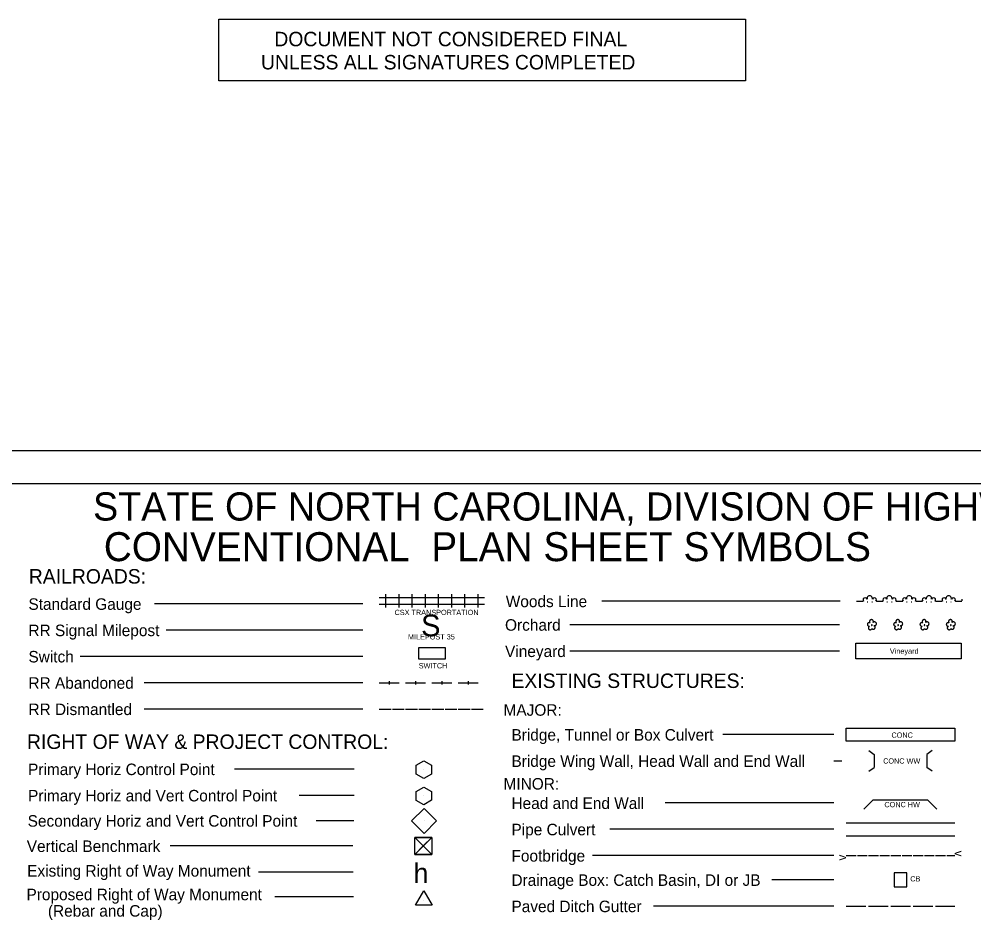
# Model space of a CAD drawing. Extents: x 885291.5 to 885334, y 651348 to 651383.7.
# Drawn here: x 885305.76 to 885323.9, y 651366.57 to 651383.73 of the extents above; entities that cross this region are included whole.
import ezdxf

# ---------------------------------------------------------------- set-up
doc = ezdxf.new("R2010")
doc.units = 0
for name, color, linetype in [('Default', 7, 'Continuous'), ('Sheet Sticker Exception Certification CELL', 7, 'Continuous'), ('Sheet Symbology CELL', 7, 'Continuous'), ('Stewart Plot Border Xerox6279 and LJ5000', 7, 'Continuous')]:
    doc.layers.add(name, color=color, linetype=linetype)

msp = doc.modelspace()

# ---------------------------------------------------------------- linework, layer by layer
at = {"layer": 'Default'}
for p, q in [((885313.448, 651369.463), (885313.448, 651369.463)), ((885313.448, 651368.964), (885313.448, 651368.964)), ((885313.451, 651368.487), (885313.451, 651368.487)), ((885313.439, 651368.012), (885313.439, 651368.012))]:
    msp.add_line(p, q, dxfattribs=at)
for points in [[(885313.448, 651369.297), (885313.303, 651369.379), (885313.303, 651369.546), (885313.448, 651369.63), (885313.593, 651369.547), (885313.593, 651369.379), (885313.448, 651369.297)], [(885313.601, 651368.174), (885313.276, 651367.85), (885313.438, 651368.012), (885313.601, 651367.85), (885313.276, 651368.174)], [(885313.438, 651368.012), (885313.601, 651368.174), (885313.276, 651368.174), (885313.438, 651368.012)], [(885313.438, 651368.012), (885313.276, 651367.85), (885313.601, 651367.85), (885313.438, 651368.012)]]:
    msp.add_lwpolyline(points, dxfattribs=at)
for points in [[(885313.302, 651369.049), (885313.449, 651369.13), (885313.595, 651369.05), (885313.593, 651368.882), (885313.446, 651368.796), (885313.302, 651368.878)], [(885313.216, 651368.488), (885313.452, 651368.724), (885313.689, 651368.488), (885313.453, 651368.251)], [(885313.276, 651368.174), (885313.601, 651368.174), (885313.601, 651367.85), (885313.276, 651367.85)]]:
    msp.add_lwpolyline(points, close=True, dxfattribs=at)
at = {"layer": 'Sheet Sticker Exception Certification CELL'}
for p, q in [((885309.555, 651382.553), (885309.555, 651383.728)), ((885309.555, 651383.728), (885319.556, 651383.728)), ((885319.556, 651383.727), (885319.556, 651382.552)), ((885319.556, 651382.553), (885309.555, 651382.553))]:
    msp.add_line(p, q, dxfattribs=at)
at = {"layer": 'Sheet Symbology CELL'}
for p, q in [((885312.602, 651372.732), (885312.852, 651372.732)), ((885312.727, 651372.545), (885312.727, 651372.795)), ((885312.852, 651372.732), (885313.102, 651372.732)), ((885312.977, 651372.545), (885312.977, 651372.795)), ((885313.102, 651372.732), (885313.352, 651372.732)), ((885313.227, 651372.545), (885313.227, 651372.795)), ((885313.352, 651372.732), (885313.602, 651372.732)), ((885313.477, 651372.545), (885313.477, 651372.795)), ((885313.602, 651372.732), (885313.852, 651372.732)), ((885313.727, 651372.545), (885313.727, 651372.795)), ((885313.852, 651372.732), (885314.102, 651372.732)), ((885313.977, 651372.545), (885313.977, 651372.795)), ((885314.102, 651372.732), (885314.352, 651372.732)), ((885314.227, 651372.545), (885314.227, 651372.795)), ((885314.352, 651372.732), (885314.602, 651372.732)), ((885314.477, 651372.545), (885314.477, 651372.795)), ((885321.358, 651372.664), (885316.83, 651372.664)), ((885321.668, 651372.664), (885321.793, 651372.664)), ((885321.866, 651372.652), (885321.879, 651372.652)), ((885321.954, 651372.652), (885321.966, 651372.652)), ((885322.043, 651372.664), (885322.168, 651372.664)), ((885322.241, 651372.652), (885322.254, 651372.652)), ((885322.329, 651372.652), (885322.341, 651372.652)), ((885322.418, 651372.664), (885322.543, 651372.664)), ((885322.616, 651372.652), (885322.629, 651372.652)), ((885322.704, 651372.652), (885322.716, 651372.652)), ((885322.793, 651372.664), (885322.918, 651372.664)), ((885322.991, 651372.652), (885323.004, 651372.652)), ((885323.079, 651372.652), (885323.091, 651372.652)), ((885323.168, 651372.664), (885323.293, 651372.664)), ((885323.366, 651372.652), (885323.379, 651372.652)), ((885323.454, 651372.652), (885323.466, 651372.652)), ((885323.543, 651372.664), (885323.668, 651372.664)), ((885312.292, 651372.613), (885308.332, 651372.613)), ((885312.602, 651372.607), (885312.852, 651372.607)), ((885312.852, 651372.607), (885313.102, 651372.607)), ((885313.102, 651372.607), (885313.352, 651372.607)), ((885313.352, 651372.607), (885313.602, 651372.607)), ((885313.602, 651372.607), (885313.852, 651372.607)), ((885313.852, 651372.607), (885314.102, 651372.607)), ((885314.102, 651372.607), (885314.352, 651372.607)), ((885314.352, 651372.607), (885314.602, 651372.607)), ((885312.292, 651372.113), (885308.553, 651372.113)), ((885321.344, 651372.216), (885316.22, 651372.216)), ((885312.292, 651371.613), (885306.919, 651371.613)), ((885321.344, 651371.716), (885316.22, 651371.716)), ((885312.292, 651371.113), (885308.138, 651371.113)), ((885312.602, 651371.113), (885312.977, 651371.113)), ((885312.789, 651371.144), (885312.789, 651371.082)), ((885313.102, 651371.113), (885313.477, 651371.113)), ((885313.289, 651371.144), (885313.289, 651371.082)), ((885313.602, 651371.113), (885313.977, 651371.113)), ((885313.789, 651371.144), (885313.789, 651371.082)), ((885314.102, 651371.113), (885314.477, 651371.113)), ((885314.289, 651371.144), (885314.289, 651371.082)), ((885312.292, 651370.613), (885308.138, 651370.613)), ((885312.292, 651370.613), (885308.138, 651370.613)), ((885312.602, 651370.613), (885312.827, 651370.613)), ((885312.852, 651370.613), (885313.077, 651370.613)), ((885313.102, 651370.613), (885313.327, 651370.613)), ((885313.352, 651370.613), (885313.577, 651370.613)), ((885313.602, 651370.613), (885313.827, 651370.613)), ((885313.852, 651370.613), (885314.077, 651370.613)), ((885314.102, 651370.613), (885314.327, 651370.613)), ((885314.352, 651370.613), (885314.577, 651370.613)), ((885321.236, 651370.128), (885319.125, 651370.128)), ((885321.897, 651369.825), (885322, 651369.753)), ((885322, 651369.753), (885322, 651369.503)), ((885323.102, 651369.825), (885323, 651369.753)), ((885323, 651369.753), (885323, 651369.503)), ((885321.236, 651369.628), (885321.386, 651369.628)), ((885312.125, 651369.473), (885309.849, 651369.473)), ((885321.897, 651369.432), (885322, 651369.503)), ((885323.102, 651369.432), (885323, 651369.503)), ((885312.125, 651368.973), (885311.077, 651368.973)), ((885321.807, 651368.714), (885321.984, 651368.891)), ((885321.984, 651368.891), (885323.015, 651368.891)), ((885323.015, 651368.891), (885323.192, 651368.714)), ((885321.236, 651368.829), (885318.028, 651368.829)), ((885312.117, 651368.492), (885311.403, 651368.492)), ((885321.236, 651368.329), (885316.981, 651368.329)), ((885321.468, 651368.454), (885323.531, 651368.454)), ((885321.468, 651368.204), (885323.531, 651368.204)), ((885312.1, 651368.012), (885308.629, 651368.012)), ((885321.236, 651367.829), (885316.649, 651367.829)), ((885321.468, 651367.829), (885321.656, 651367.829)), ((885321.681, 651367.829), (885321.868, 651367.829)), ((885321.893, 651367.829), (885322.081, 651367.829)), ((885322.106, 651367.829), (885322.293, 651367.829)), ((885322.318, 651367.829), (885322.506, 651367.829)), ((885322.531, 651367.829), (885322.718, 651367.829)), ((885322.743, 651367.829), (885322.931, 651367.829)), ((885322.956, 651367.829), (885323.143, 651367.829)), ((885323.168, 651367.829), (885323.356, 651367.829)), ((885323.381, 651367.829), (885323.531, 651367.829)), ((885312.108, 651367.512), (885310.306, 651367.512)), ((885321.236, 651367.368), (885320.056, 651367.368)), ((885312.11, 651367.043), (885310.617, 651367.043)), ((885313.448, 651366.977), (885313.448, 651366.977)), ((885321.236, 651366.868), (885317.812, 651366.868)), ((885321.468, 651366.868), (885321.843, 651366.868)), ((885321.893, 651366.868), (885322.268, 651366.868)), ((885322.318, 651366.868), (885322.693, 651366.868)), ((885322.743, 651366.868), (885323.118, 651366.868)), ((885323.168, 651366.868), (885323.531, 651366.868))]:
    msp.add_line(p, q, dxfattribs=at)
for points in [[(885333.401, 651374.896), (885295.901, 651374.896), (885295.901, 651348.671), (885333.401, 651348.671)], [(885313.352, 651371.787), (885313.852, 651371.787), (885313.852, 651371.56), (885313.352, 651371.56)], [(885322.379, 651367.235), (885322.62, 651367.235), (885322.62, 651367.501), (885322.379, 651367.501)], [(885313.292, 651366.887), (885313.448, 651367.157), (885313.604, 651366.887)]]:
    msp.add_lwpolyline(points, close=True, dxfattribs=at)
for points in [[(885321.98, 651372.26), (885321.984, 651372.267), (885321.985, 651372.275), (885321.984, 651372.282), (885321.982, 651372.29), (885321.979, 651372.296), (885321.975, 651372.302), (885321.969, 651372.307), (885321.962, 651372.311), (885321.954, 651372.314), (885321.947, 651372.314), (885321.94, 651372.312), (885321.932, 651372.31), (885321.926, 651372.306), (885321.92, 651372.301), (885321.916, 651372.294), (885321.914, 651372.287), (885321.912, 651372.28), (885321.912, 651372.272), (885321.914, 651372.265), (885321.917, 651372.259), (885321.922, 651372.251), (885321.916, 651372.255), (885321.909, 651372.256), (885321.901, 651372.256), (885321.895, 651372.254), (885321.889, 651372.251), (885321.882, 651372.246), (885321.877, 651372.241), (885321.874, 651372.235), (885321.872, 651372.229), (885321.871, 651372.22), (885321.872, 651372.214), (885321.875, 651372.207), (885321.88, 651372.201), (885321.884, 651372.196), (885321.89, 651372.192), (885321.897, 651372.189), (885321.904, 651372.187), (885321.911, 651372.187), (885321.905, 651372.185), (885321.899, 651372.18), (885321.895, 651372.175), (885321.892, 651372.167), (885321.89, 651372.16), (885321.89, 651372.154), (885321.891, 651372.146), (885321.895, 651372.14), (885321.899, 651372.134), (885321.904, 651372.129), (885321.91, 651372.125), (885321.916, 651372.122), (885321.924, 651372.122), (885321.931, 651372.122), (885321.937, 651372.124), (885321.944, 651372.129), (885321.95, 651372.132), (885321.956, 651372.144)], [(885322.48, 651372.26), (885322.484, 651372.267), (885322.485, 651372.275), (885322.484, 651372.282), (885322.482, 651372.29), (885322.479, 651372.296), (885322.475, 651372.302), (885322.469, 651372.307), (885322.462, 651372.311), (885322.454, 651372.314), (885322.447, 651372.314), (885322.44, 651372.312), (885322.432, 651372.31), (885322.426, 651372.306), (885322.42, 651372.301), (885322.416, 651372.294), (885322.414, 651372.287), (885322.412, 651372.28), (885322.412, 651372.272), (885322.414, 651372.265), (885322.417, 651372.259), (885322.422, 651372.251), (885322.416, 651372.255), (885322.409, 651372.256), (885322.401, 651372.256), (885322.395, 651372.254), (885322.389, 651372.251), (885322.382, 651372.246), (885322.377, 651372.241), (885322.374, 651372.235), (885322.372, 651372.229), (885322.371, 651372.22), (885322.372, 651372.214), (885322.375, 651372.207), (885322.38, 651372.201), (885322.384, 651372.196), (885322.39, 651372.192), (885322.397, 651372.189), (885322.404, 651372.187), (885322.411, 651372.187), (885322.405, 651372.185), (885322.399, 651372.18), (885322.395, 651372.175), (885322.392, 651372.167), (885322.39, 651372.16), (885322.39, 651372.154), (885322.391, 651372.146), (885322.395, 651372.14), (885322.399, 651372.134), (885322.404, 651372.129), (885322.41, 651372.125), (885322.416, 651372.122), (885322.424, 651372.122), (885322.431, 651372.122), (885322.437, 651372.124), (885322.444, 651372.129), (885322.45, 651372.132), (885322.456, 651372.144)], [(885322.98, 651372.26), (885322.984, 651372.267), (885322.985, 651372.275), (885322.984, 651372.282), (885322.982, 651372.29), (885322.979, 651372.296), (885322.975, 651372.302), (885322.969, 651372.307), (885322.962, 651372.311), (885322.954, 651372.314), (885322.947, 651372.314), (885322.94, 651372.312), (885322.932, 651372.31), (885322.926, 651372.306), (885322.92, 651372.301), (885322.916, 651372.294), (885322.914, 651372.287), (885322.912, 651372.28), (885322.912, 651372.272), (885322.914, 651372.265), (885322.917, 651372.259), (885322.922, 651372.251), (885322.916, 651372.255), (885322.909, 651372.256), (885322.901, 651372.256), (885322.895, 651372.254), (885322.889, 651372.251), (885322.882, 651372.246), (885322.877, 651372.241), (885322.874, 651372.235), (885322.872, 651372.229), (885322.871, 651372.22), (885322.872, 651372.214), (885322.875, 651372.207), (885322.88, 651372.201), (885322.884, 651372.196), (885322.89, 651372.192), (885322.897, 651372.189), (885322.904, 651372.187), (885322.911, 651372.187), (885322.905, 651372.185), (885322.899, 651372.18), (885322.895, 651372.175), (885322.892, 651372.167), (885322.89, 651372.16), (885322.89, 651372.154), (885322.891, 651372.146), (885322.895, 651372.14), (885322.899, 651372.134), (885322.904, 651372.129), (885322.91, 651372.125), (885322.916, 651372.122), (885322.924, 651372.122), (885322.931, 651372.122), (885322.937, 651372.124), (885322.944, 651372.129), (885322.95, 651372.132), (885322.956, 651372.144)], [(885323.48, 651372.26), (885323.484, 651372.267), (885323.485, 651372.275), (885323.484, 651372.282), (885323.482, 651372.29), (885323.479, 651372.296), (885323.475, 651372.302), (885323.469, 651372.307), (885323.462, 651372.311), (885323.454, 651372.314), (885323.447, 651372.314), (885323.44, 651372.312), (885323.432, 651372.31), (885323.426, 651372.306), (885323.42, 651372.301), (885323.416, 651372.294), (885323.414, 651372.287), (885323.412, 651372.28), (885323.412, 651372.272), (885323.414, 651372.265), (885323.417, 651372.259), (885323.422, 651372.251), (885323.416, 651372.255), (885323.409, 651372.256), (885323.401, 651372.256), (885323.395, 651372.254), (885323.389, 651372.251), (885323.382, 651372.246), (885323.377, 651372.241), (885323.374, 651372.235), (885323.372, 651372.229), (885323.371, 651372.22), (885323.372, 651372.214), (885323.375, 651372.207), (885323.38, 651372.201), (885323.384, 651372.196), (885323.39, 651372.192), (885323.397, 651372.189), (885323.404, 651372.187), (885323.411, 651372.187), (885323.405, 651372.185), (885323.399, 651372.18), (885323.395, 651372.175), (885323.392, 651372.167), (885323.39, 651372.16), (885323.39, 651372.154), (885323.391, 651372.146), (885323.395, 651372.14), (885323.399, 651372.134), (885323.404, 651372.129), (885323.41, 651372.125), (885323.416, 651372.122), (885323.424, 651372.122), (885323.431, 651372.122), (885323.437, 651372.124), (885323.444, 651372.129), (885323.45, 651372.132), (885323.456, 651372.144)], [(885321.959, 651372.216), (885321.955, 651372.216), (885321.952, 651372.215), (885321.95, 651372.214), (885321.95, 651372.21), (885321.95, 651372.207), (885321.952, 651372.205), (885321.956, 651372.205), (885321.959, 651372.205), (885321.961, 651372.207), (885321.962, 651372.211), (885321.961, 651372.214), (885321.959, 651372.216)], [(885321.956, 651372.144), (885321.971, 651372.135), (885321.979, 651372.132), (885321.986, 651372.131), (885321.994, 651372.132), (885322, 651372.135), (885322.006, 651372.139), (885322.012, 651372.144), (885322.016, 651372.15), (885322.019, 651372.156), (885322.021, 651372.164), (885322.02, 651372.171), (885322.019, 651372.179), (885322.014, 651372.186), (885322.01, 651372.191), (885322.004, 651372.195), (885321.996, 651372.199), (885322.004, 651372.197), (885322.012, 651372.197), (885322.019, 651372.2), (885322.026, 651372.204), (885322.032, 651372.207), (885322.037, 651372.214), (885322.041, 651372.221), (885322.042, 651372.229), (885322.044, 651372.236), (885322.042, 651372.244), (885322.04, 651372.251), (885322.035, 651372.257), (885322.029, 651372.264), (885322.022, 651372.267), (885322.015, 651372.27), (885322.007, 651372.271), (885322, 651372.271), (885321.992, 651372.269), (885321.986, 651372.265), (885321.98, 651372.26)], [(885322.459, 651372.216), (885322.455, 651372.216), (885322.452, 651372.215), (885322.45, 651372.214), (885322.45, 651372.21), (885322.45, 651372.207), (885322.452, 651372.205), (885322.456, 651372.205), (885322.459, 651372.205), (885322.461, 651372.207), (885322.462, 651372.211), (885322.461, 651372.214), (885322.459, 651372.216)], [(885322.456, 651372.144), (885322.471, 651372.135), (885322.479, 651372.132), (885322.486, 651372.131), (885322.494, 651372.132), (885322.5, 651372.135), (885322.506, 651372.139), (885322.512, 651372.144), (885322.516, 651372.15), (885322.519, 651372.156), (885322.521, 651372.164), (885322.52, 651372.171), (885322.519, 651372.179), (885322.514, 651372.186), (885322.51, 651372.191), (885322.504, 651372.195), (885322.496, 651372.199), (885322.504, 651372.197), (885322.512, 651372.197), (885322.519, 651372.2), (885322.526, 651372.204), (885322.532, 651372.207), (885322.537, 651372.214), (885322.541, 651372.221), (885322.542, 651372.229), (885322.544, 651372.236), (885322.542, 651372.244), (885322.54, 651372.251), (885322.535, 651372.257), (885322.529, 651372.264), (885322.522, 651372.267), (885322.515, 651372.27), (885322.507, 651372.271), (885322.5, 651372.271), (885322.492, 651372.269), (885322.486, 651372.265), (885322.48, 651372.26)], [(885322.959, 651372.216), (885322.955, 651372.216), (885322.952, 651372.215), (885322.95, 651372.214), (885322.95, 651372.21), (885322.95, 651372.207), (885322.952, 651372.205), (885322.956, 651372.205), (885322.959, 651372.205), (885322.961, 651372.207), (885322.962, 651372.211), (885322.961, 651372.214), (885322.959, 651372.216)], [(885322.956, 651372.144), (885322.971, 651372.135), (885322.979, 651372.132), (885322.986, 651372.131), (885322.994, 651372.132), (885323, 651372.135), (885323.006, 651372.139), (885323.012, 651372.144), (885323.016, 651372.15), (885323.019, 651372.156), (885323.021, 651372.164), (885323.02, 651372.171), (885323.019, 651372.179), (885323.014, 651372.186), (885323.01, 651372.191), (885323.004, 651372.195), (885322.996, 651372.199), (885323.004, 651372.197), (885323.012, 651372.197), (885323.019, 651372.2), (885323.026, 651372.204), (885323.032, 651372.207), (885323.037, 651372.214), (885323.041, 651372.221), (885323.042, 651372.229), (885323.044, 651372.236), (885323.042, 651372.244), (885323.04, 651372.251), (885323.035, 651372.257), (885323.029, 651372.264), (885323.022, 651372.267), (885323.015, 651372.27), (885323.007, 651372.271), (885323, 651372.271), (885322.992, 651372.269), (885322.986, 651372.265), (885322.98, 651372.26)], [(885323.459, 651372.216), (885323.455, 651372.216), (885323.452, 651372.215), (885323.45, 651372.214), (885323.45, 651372.21), (885323.45, 651372.207), (885323.452, 651372.205), (885323.456, 651372.205), (885323.459, 651372.205), (885323.461, 651372.207), (885323.462, 651372.211), (885323.461, 651372.214), (885323.459, 651372.216)], [(885323.456, 651372.144), (885323.471, 651372.135), (885323.479, 651372.132), (885323.486, 651372.131), (885323.494, 651372.132), (885323.5, 651372.135), (885323.506, 651372.139), (885323.512, 651372.144), (885323.516, 651372.15), (885323.519, 651372.156), (885323.521, 651372.164), (885323.52, 651372.171), (885323.519, 651372.179), (885323.514, 651372.186), (885323.51, 651372.191), (885323.504, 651372.195), (885323.496, 651372.199), (885323.504, 651372.197), (885323.512, 651372.197), (885323.519, 651372.2), (885323.526, 651372.204), (885323.532, 651372.207), (885323.537, 651372.214), (885323.541, 651372.221), (885323.542, 651372.229), (885323.544, 651372.236), (885323.542, 651372.244), (885323.54, 651372.251), (885323.535, 651372.257), (885323.529, 651372.264), (885323.522, 651372.267), (885323.515, 651372.27), (885323.507, 651372.271), (885323.5, 651372.271), (885323.492, 651372.269), (885323.486, 651372.265), (885323.48, 651372.26)], [(885321.654, 651371.866), (885323.654, 651371.866), (885323.654, 651371.566), (885321.654, 651371.566), (885321.654, 651371.866)], [(885321.468, 651370.253), (885323.531, 651370.253), (885323.531, 651370.003), (885321.468, 651370.003), (885321.468, 651370.253)]]:
    msp.add_lwpolyline(points, dxfattribs=at)
for centre, radius, start, end in [((885321.829, 651372.69), 0.0395, 18.435, 219.2315), ((885321.916, 651372.715), 0.0515, 345.9638, 194.0362), ((885322.004, 651372.69), 0.0395, 320.7685, 161.5651), ((885322.204, 651372.69), 0.0395, 18.435, 219.2315), ((885322.291, 651372.715), 0.0515, 345.9638, 194.0362), ((885322.379, 651372.69), 0.0395, 320.7685, 161.5651), ((885322.579, 651372.69), 0.0395, 18.435, 219.2315), ((885322.666, 651372.715), 0.0515, 345.9638, 194.0362), ((885322.754, 651372.69), 0.0395, 320.7685, 161.5651), ((885322.954, 651372.69), 0.0395, 18.435, 219.2315), ((885323.041, 651372.715), 0.0515, 345.9638, 194.0362), ((885323.129, 651372.69), 0.0395, 320.7685, 161.5651), ((885323.329, 651372.69), 0.0395, 18.435, 219.2315), ((885323.416, 651372.715), 0.0515, 345.9638, 194.0362), ((885323.504, 651372.69), 0.0395, 320.7685, 161.5651), ((885323.704, 651372.69), 0.0395, 156.251, 203.749)]:
    msp.add_arc(centre, radius, start, end, dxfattribs=at)
at = {"layer": 'Stewart Plot Border Xerox6279 and LJ5000'}
msp.add_lwpolyline([(885291.526, 651348.021), (885334.026, 651348.021), (885334.026, 651375.521), (885291.526, 651375.521)], close=True, dxfattribs=at)

# ---------------------------------------------------------------- texts
at = {"layer": 'Sheet Sticker Exception Certification CELL'}
for s, p in [('DOCUMENT NOT CONSIDERED FINAL', (885310.608, 651383.211)), ('UNLESS ALL SIGNATURES COMPLETED', (885310.354, 651382.771))]:
    msp.add_text(s, height=0.275, rotation=0, dxfattribs=at).set_placement(p)
at = {"layer": 'Sheet Symbology CELL'}
for s, height, p in [('STATE OF NORTH CAROLINA, DIVISION OF HIGHWAYS', 0.53547, (885307.165, 651374.197)), ('CONVENTIONAL  PLAN SHEET SYMBOLS', 0.55081, (885307.369, 651373.425)), ('RAILROADS:', 0.275, (885305.945, 651372.999)), ('Standard Gauge', 0.21875, (885305.938, 651372.5)), ('Woods Line', 0.2188, (885315.004, 651372.551)), ('S', 0.412, (885313.396, 651371.997)), ('Orchard', 0.2188, (885314.99, 651372.103)), ('RR Signal Milepost', 0.21875, (885305.938, 651372)), ('Vineyard', 0.2188, (885314.99, 651371.603)), ('Switch', 0.2188, (885305.938, 651371.5)), ('RR Abandoned', 0.21875, (885305.938, 651371)), ('EXISTING STRUCTURES:', 0.275, (885315.112, 651371.015)), ('RR Dismantled', 0.21875, (885305.938, 651370.5)), ('MAJOR:', 0.2188, (885314.961, 651370.487)), ('RIGHT OF WAY & PROJECT CONTROL:', 0.275, (885305.91, 651369.856)), ('Bridge, Tunnel or Box Culvert', 0.21875, (885315.112, 651370.015)), ('CONC', 0.1, (885322.329, 651370.069)), ('Bridge Wing Wall, Head Wall and End Wall', 0.21875, (885315.112, 651369.515)), ('Primary Horiz Control Point', 0.21875, (885305.931, 651369.359)), ('MINOR:', 0.2188, (885314.961, 651369.084)), ('Primary Horiz and Vert Control Point', 0.21875, (885305.931, 651368.859)), ('Head and End Wall', 0.21875, (885315.112, 651368.715)), ('Secondary Horiz and Vert Control Point', 0.21875, (885305.923, 651368.379)), ('Pipe Culvert', 0.21875, (885315.112, 651368.215)), ('Vertical Benchmark', 0.21875, (885305.906, 651367.898)), ('Footbridge', 0.2188, (885315.112, 651367.715)), ('Existing Right of Way Monument', 0.21875, (885305.914, 651367.43)), ('h', 0.375, (885313.254, 651367.308)), ('Drainage Box: Catch Basin, DI or JB', 0.21875, (885315.112, 651367.254)), ('Proposed Right of Way Monument', 0.21875, (885305.901, 651366.981)), ('     (Rebar and Cap)', 0.21875, (885305.901, 651366.669)), ('Paved Ditch Gutter', 0.21875, (885315.112, 651366.754))]:
    msp.add_text(s, height=height, dxfattribs=at).set_placement(p)
for s, height, rotation, p in [('CSX TRANSPORTATION', 0.1, 360, (885312.891, 651372.401)), ('MILEPOST 35', 0.1, 360, (885313.146, 651371.937)), ('Vineyard', 0.1, 0, (885322.299, 651371.666)), ('SWITCH', 0.1, 360, (885313.351, 651371.387)), ('CONC WW', 0.1, 0, (885322.171, 651369.578)), ('CONC HW', 0.1, 360, (885322.195, 651368.749)), ('v', 0.165, 89.7591, (885321.468, 651367.735)), ('v', 0.165, 270.2409, (885323.531, 651367.922)), ('CB', 0.1, 360, (885322.686, 651367.338))]:
    msp.add_text(s, height=height, rotation=rotation, dxfattribs=at).set_placement(p)

doc.saveas('drawing.dxf')
